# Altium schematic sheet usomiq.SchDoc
size A4
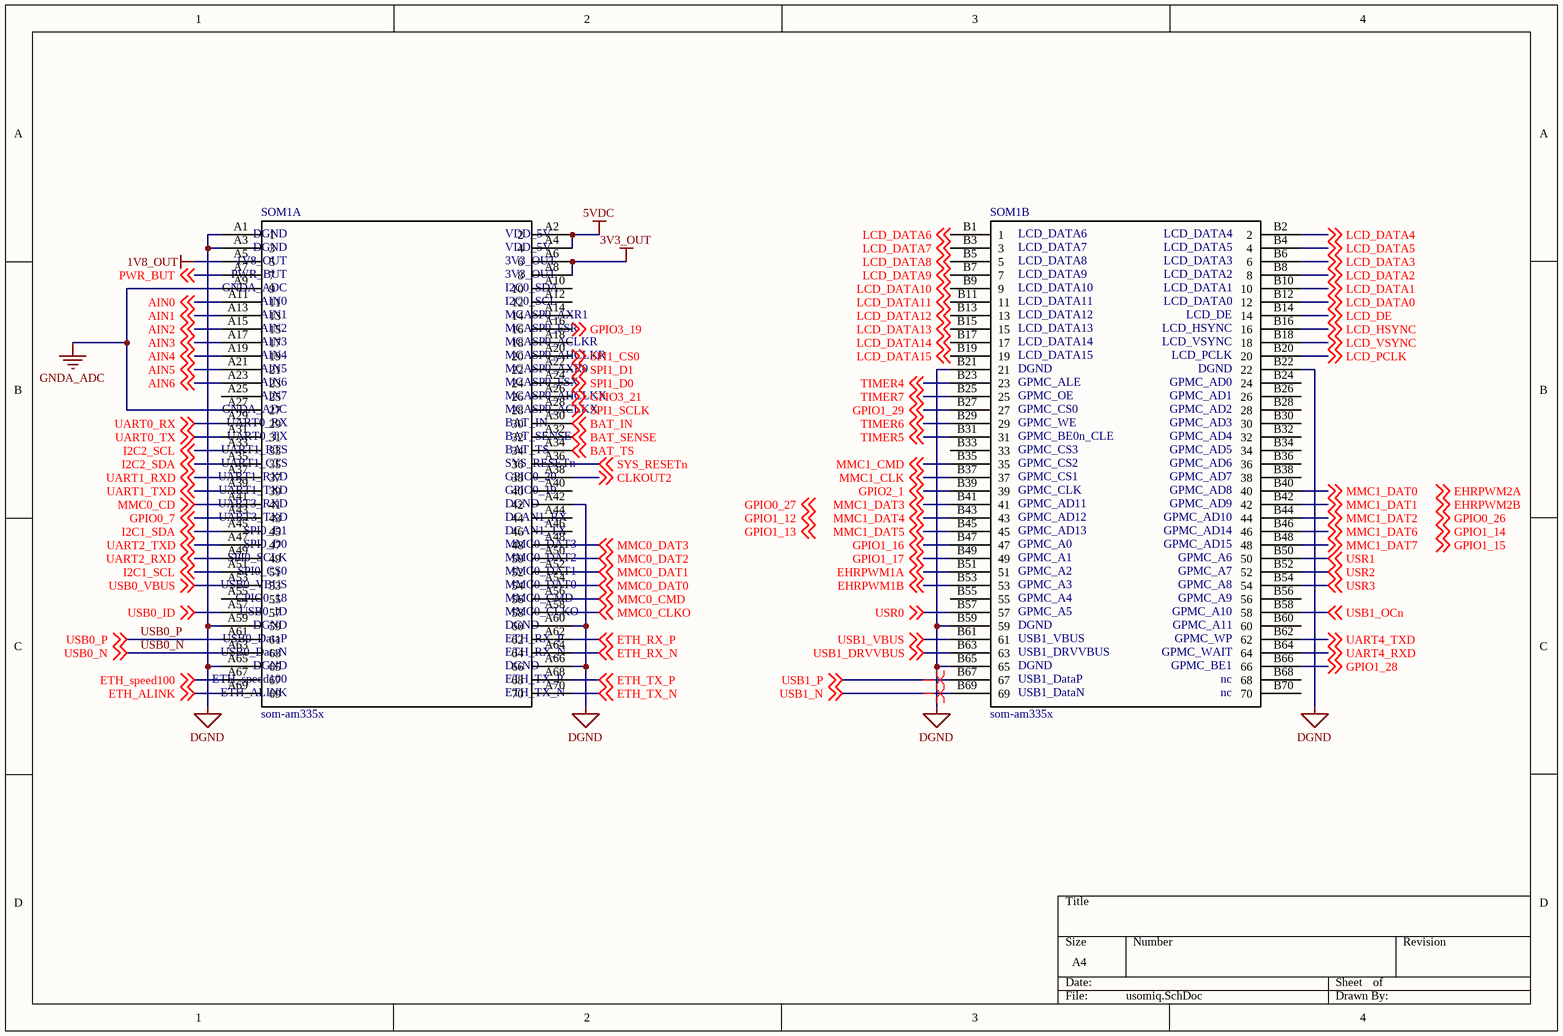
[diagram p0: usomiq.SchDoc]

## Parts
SOM1  som-am335x  [am3359_module-sockets]  (parts A,B of 2)

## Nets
1V8_OUT: SOM1.A5(5)
3V3_OUT: SOM1.A6(6) SOM1.A8(8)
5VDC: SOM1.A2(2) SOM1.A4(4)
DGND: SOM1.A1(1) SOM1.A3(3) SOM1.A42(42) SOM1.A59(59) SOM1.A60(60) SOM1.A65(65) SOM1.A66(66) SOM1.B21(21) SOM1.B22(22) SOM1.B59(59) SOM1.B65(65)
GNDA_ADC: SOM1.A9(9) SOM1.A27(27)
AIN0: SOM1.A11(11) ; off-sheet AIN0
AIN1: SOM1.A13(13) ; off-sheet AIN1
AIN2: SOM1.A15(15) ; off-sheet AIN2
AIN3: SOM1.A17(17) ; off-sheet AIN3
AIN4: SOM1.A19(19) ; off-sheet AIN4
AIN5: SOM1.A21(21) ; off-sheet AIN5
AIN6: SOM1.A23(23) ; off-sheet AIN6
BAT_IN: SOM1.A30(30) ; off-sheet BAT_IN
BAT_SENSE: SOM1.A32(32) ; off-sheet BAT_SENSE
BAT_TS: SOM1.A34(34) ; off-sheet BAT_TS
CLKOUT2: SOM1.A38(38) ; off-sheet CLKOUT2
EHRPWM1A: SOM1.B51(51) ; off-sheet EHRPWM1A
EHRPWM1B: SOM1.B53(53) ; off-sheet EHRPWM1B
ETH_ALINK: SOM1.A69(69) ; off-sheet ETH_ALINK
ETH_RX_N: SOM1.A64(64) ; off-sheet ETH_RX_N
ETH_RX_P: SOM1.A62(62) ; off-sheet ETH_RX_P
ETH_speed100: SOM1.A67(67) ; off-sheet ETH_speed100
ETH_TX_N: SOM1.A70(70) ; off-sheet ETH_TX_N
ETH_TX_P: SOM1.A68(68) ; off-sheet ETH_TX_P
GPIO0_7: SOM1.A43(43) ; off-sheet GPIO0_7
GPIO1_16: SOM1.B47(47) ; off-sheet GPIO1_16
GPIO1_17: SOM1.B49(49) ; off-sheet GPIO1_17
GPIO1_28: SOM1.B66(66) ; off-sheet GPIO1_28
GPIO1_29: SOM1.B27(27) ; off-sheet GPIO1_29
GPIO2_1: SOM1.B39(39) ; off-sheet GPIO2_1
GPIO3_19: SOM1.A16(16) ; off-sheet GPIO3_19
GPIO3_21: SOM1.A26(26) ; off-sheet GPIO3_21
I2C1_SCL: SOM1.A51(51) ; off-sheet I2C1_SCL
I2C1_SDA: SOM1.A45(45) ; off-sheet I2C1_SDA
I2C2_SCL: SOM1.A33(33) ; off-sheet I2C2_SCL
I2C2_SDA: SOM1.A35(35) ; off-sheet I2C2_SDA
LCD_DATA0: SOM1.B12(12) ; off-sheet LCD_DATA0
LCD_DATA1: SOM1.B10(10) ; off-sheet LCD_DATA1
LCD_DATA2: SOM1.B8(8) ; off-sheet LCD_DATA2
LCD_DATA3: SOM1.B6(6) ; off-sheet LCD_DATA3
LCD_DATA4: SOM1.B2(2) ; off-sheet LCD_DATA4
LCD_DATA5: SOM1.B4(4) ; off-sheet LCD_DATA5
LCD_DATA6: SOM1.B1(1) ; off-sheet LCD_DATA6
LCD_DATA7: SOM1.B3(3) ; off-sheet LCD_DATA7
LCD_DATA8: SOM1.B5(5) ; off-sheet LCD_DATA8
LCD_DATA9: SOM1.B7(7) ; off-sheet LCD_DATA9
LCD_DATA10: SOM1.B9(9) ; off-sheet LCD_DATA10
LCD_DATA11: SOM1.B11(11) ; off-sheet LCD_DATA11
LCD_DATA12: SOM1.B13(13) ; off-sheet LCD_DATA12
LCD_DATA13: SOM1.B15(15) ; off-sheet LCD_DATA13
LCD_DATA14: SOM1.B17(17) ; off-sheet LCD_DATA14
LCD_DATA15: SOM1.B19(19) ; off-sheet LCD_DATA15
LCD_DE: SOM1.B14(14) ; off-sheet LCD_DE
LCD_HSYNC: SOM1.B16(16) ; off-sheet LCD_HSYNC
LCD_PCLK: SOM1.B20(20) ; off-sheet LCD_PCLK
LCD_VSYNC: SOM1.B18(18) ; off-sheet LCD_VSYNC
MMC0_CD: SOM1.A41(41) ; off-sheet MMC0_CD
MMC0_CLKO: SOM1.A58(58) ; off-sheet MMC0_CLKO
MMC0_CMD: SOM1.A56(56) ; off-sheet MMC0_CMD
MMC0_DAT0: SOM1.A54(54) ; off-sheet MMC0_DAT0
MMC0_DAT1: SOM1.A52(52) ; off-sheet MMC0_DAT1
MMC0_DAT2: SOM1.A50(50) ; off-sheet MMC0_DAT2
MMC0_DAT3: SOM1.A48(48) ; off-sheet MMC0_DAT3
MMC1_CLK: SOM1.B37(37) ; off-sheet MMC1_CLK
MMC1_CMD: SOM1.B35(35) ; off-sheet MMC1_CMD
MMC1_DAT0: SOM1.B40(40) ; off-sheet MMC1_DAT0
MMC1_DAT1: SOM1.B42(42) ; off-sheet MMC1_DAT1
MMC1_DAT2: SOM1.B44(44) ; off-sheet MMC1_DAT2
MMC1_DAT3: SOM1.B41(41) ; off-sheet MMC1_DAT3
MMC1_DAT4: SOM1.B43(43) ; off-sheet MMC1_DAT4
MMC1_DAT5: SOM1.B45(45) ; off-sheet MMC1_DAT5
MMC1_DAT6: SOM1.B46(46) ; off-sheet MMC1_DAT6
MMC1_DAT7: SOM1.B48(48) ; off-sheet MMC1_DAT7
PWR_BUT: SOM1.A7(7) ; off-sheet PWR_BUT
SPI1_CS0: SOM1.A20(20) ; off-sheet SPI1_CS0
SPI1_D0: SOM1.A24(24) ; off-sheet SPI1_D0
SPI1_D1: SOM1.A22(22) ; off-sheet SPI1_D1
SPI1_SCLK: SOM1.A28(28) ; off-sheet SPI1_SCLK
SYS_RESETn: SOM1.A36(36) ; off-sheet SYS_RESETn
TIMER4: SOM1.B23(23) ; off-sheet TIMER4
TIMER5: SOM1.B31(31) ; off-sheet TIMER5
TIMER6: SOM1.B29(29) ; off-sheet TIMER6
TIMER7: SOM1.B25(25) ; off-sheet TIMER7
UART0_RX: SOM1.A29(29) ; off-sheet UART0_RX
UART0_TX: SOM1.A31(31) ; off-sheet UART0_TX
UART1_RXD: SOM1.A37(37) ; off-sheet UART1_RXD
UART1_TXD: SOM1.A39(39) ; off-sheet UART1_TXD
UART2_RXD: SOM1.A49(49) ; off-sheet UART2_RXD
UART2_TXD: SOM1.A47(47) ; off-sheet UART2_TXD
UART4_RXD: SOM1.B64(64) ; off-sheet UART4_RXD
UART4_TXD: SOM1.B62(62) ; off-sheet UART4_TXD
USB0_ID: SOM1.A57(57) ; off-sheet USB0_ID
USB0_N: SOM1.A63(63) ; off-sheet USB0_N
USB0_P: SOM1.A61(61) ; off-sheet USB0_P
USB0_VBUS: SOM1.A53(53) ; off-sheet USB0_VBUS
USB1_DRVVBUS: SOM1.B63(63) ; off-sheet USB1_DRVVBUS
USB1_N: SOM1.B69(69) ; off-sheet USB1_N
USB1_OCn: SOM1.B58(58) ; off-sheet USB1_OCn
USB1_P: SOM1.B67(67) ; off-sheet USB1_P
USB1_VBUS: SOM1.B61(61) ; off-sheet USB1_VBUS
USR0: SOM1.B57(57) ; off-sheet USR0
USR1: SOM1.B50(50) ; off-sheet USR1
USR2: SOM1.B52(52) ; off-sheet USR2
USR3: SOM1.B54(54) ; off-sheet USR3

Not connected (* = marked no-connect by the designer): SOM1 A10(10) A12(12) A14(14) A18(18) A25(25) A40(40) A44(44) A46(46) A55(55) B24(24) B26(26) B28(28) B30(30) B32(32) B33(33) B34(34) B36(36) B38(38) B55(55) B56(56) B60(60) B68(68) B70(70)

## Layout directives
differential pair: USB1_N, USB1_P

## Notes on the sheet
- Labels drawn without touching a wire or pin: EHRPWM2A, EHRPWM2B, GPIO0_26, GPIO0_27, GPIO1_12, GPIO1_13, GPIO1_14, GPIO1_15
